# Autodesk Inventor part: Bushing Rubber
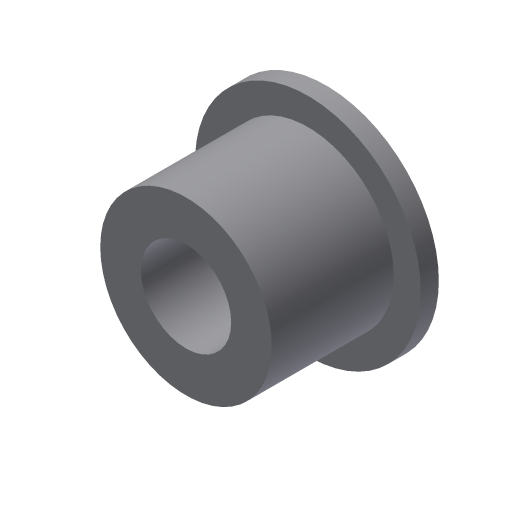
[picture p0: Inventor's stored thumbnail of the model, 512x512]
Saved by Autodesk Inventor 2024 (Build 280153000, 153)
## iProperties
Created: 2010-03
Part Number: Bushing Rubber
Document SubType Name: Modeling
Designer: bhakira
Density: 1 g/cm^3
Material: Generic
Appearance: Default
Author: bhakira
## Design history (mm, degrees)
sketch "Sketch1"
  geometry: L1 (25, 31)-(25, 27); L2 (25, 27)-(19, 27); L3 (19, 27)-(19, 0); L4 (19, 0)-(0, 0); L5 (0, 0)-(0, 31); L6 (0, 31)-(25, 31); 1 further point
  constraints: 12 end point, 1 coincident, 1 other
  dimensions: "d1" = 50 diameter of L1 L5; "d2" = 38 diameter of L3 L5; "d3" = 4 distance of L1.start L1.end; "d4" = 27 distance between parallel lines of L4 L2
revolve "Revolution1" sketch "Sketch1" stored, may be unused: angle "d5" = 90 deg
hole "Hole1" diameter "d8" = 20; stored, may be unused: countersink angle "d12" = 82 deg, drill point angle "d14" = 118 deg; dims "d6" = 10, "d7" = 10, "d9" = 6, "d10" = 34.925, "d11" = 2, "d13" = 8
body "Solid1"
